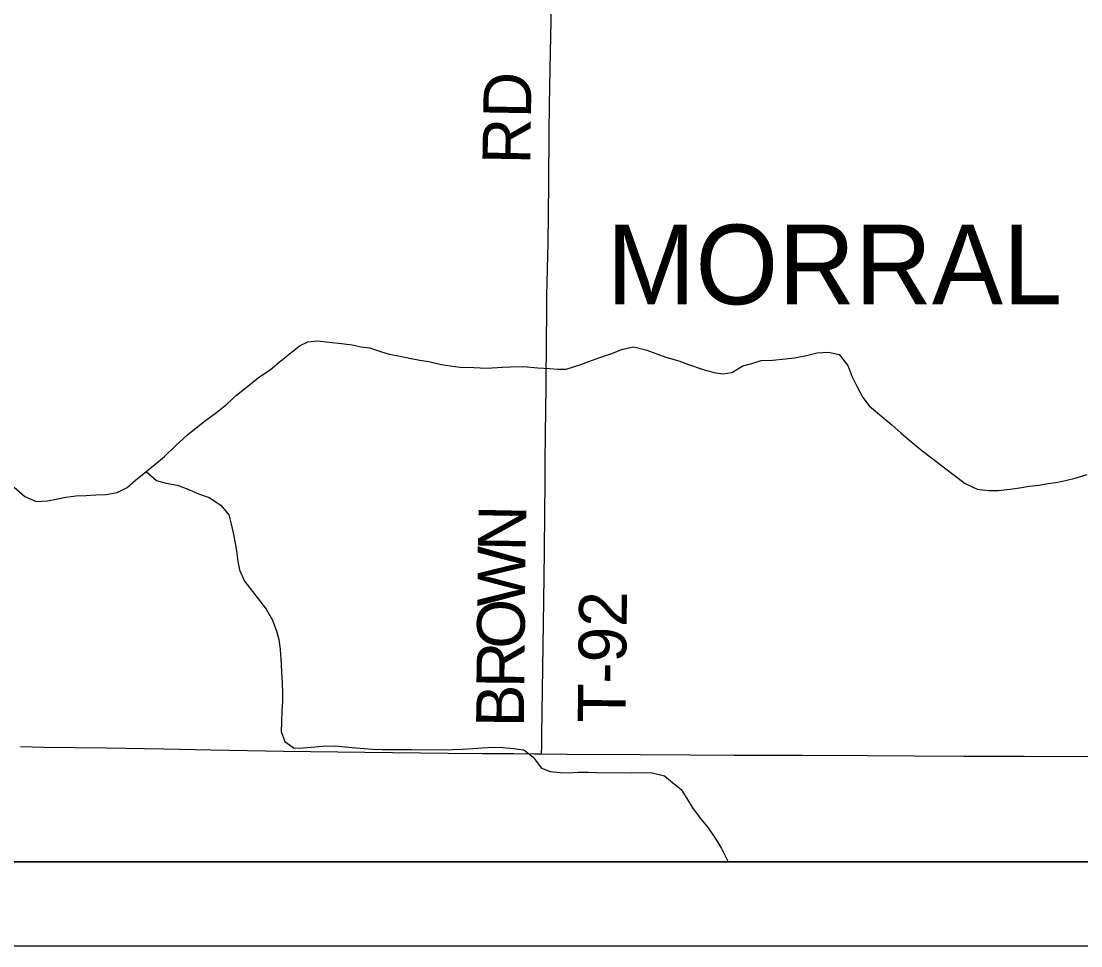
# Model space of a CAD drawing. Extents: x -17 to 88, y -5 to 22.
# Drawn here: x -14.14 to -12.88, y 14 to 15.1 of the extents above; entities that cross this region are included whole.
import ezdxf

# ---------------------------------------------------------------- set-up
doc = ezdxf.new("R2010")
doc.units = 0
for name, color, linetype in [('Default', 7, 'Continuous'), ('GM_X_Corporation_Text', 7, 'Continuous'), ('GM_X_Minor_River', 7, 'Continuous'), ('GM_X_State_Route', 7, 'Continuous'), ('GM_X_Township_Road', 7, 'Continuous'), ('GM_X_Township_Road_Text', 7, 'Continuous'), ('SH_Data', 7, 'Continuous')]:
    doc.layers.add(name, color=color, linetype=linetype)

msp = doc.modelspace()

# ---------------------------------------------------------------- linework, layer by layer
at = {"layer": 'Default'}
msp.add_lwpolyline([(-17.1602, 20.9), (-10.3602, 20.9), (-10.3602, 14.1), (-17.1602, 14.1)], close=True, dxfattribs=at)
at = {"layer": 'GM_X_Minor_River'}
for points in [[(-14.1487, 14.5458), (-14.1359, 14.5347), (-14.1227, 14.5288), (-14.109, 14.5294), (-14.0969, 14.5316), (-14.0874, 14.5338), (-14.0752, 14.5352), (-14.0631, 14.5358), (-14.0517, 14.5365), (-14.0392, 14.5371), (-14.0263, 14.5392), (-14.0144, 14.5452), (-14.0045, 14.5542), (-13.9922, 14.5639), (-13.9812, 14.5726), (-13.9697, 14.5823), (-13.9567, 14.5947), (-13.9425, 14.6079), (-13.9322, 14.6161), (-13.9211, 14.6251), (-13.9096, 14.6333), (-13.8959, 14.6446), (-13.8844, 14.6551), (-13.8568, 14.6769), (-13.8442, 14.6851), (-13.8335, 14.6945), (-13.8217, 14.7038), (-13.8091, 14.714), (-13.7995, 14.7184), (-13.7878, 14.7198), (-13.7738, 14.7181), (-13.7594, 14.7165), (-13.7465, 14.7152), (-13.7359, 14.7128), (-13.726, 14.7116), (-13.7128, 14.7069), (-13.7026, 14.7038), (-13.6894, 14.7017), (-13.6765, 14.6989), (-13.6659, 14.6969), (-13.6553, 14.6953), (-13.6409, 14.6917), (-13.6299, 14.6901), (-13.6182, 14.6885), (-13.6019, 14.6879), (-13.5867, 14.6874), (-13.5678, 14.6883), (-13.5583, 14.689), (-13.5427, 14.6892), (-13.5257, 14.6875), (-13.5117, 14.687), (-13.5018, 14.6861), (-13.492, 14.686), (-13.4745, 14.6916), (-13.4649, 14.6953), (-13.452, 14.7001), (-13.4375, 14.7049), (-13.425, 14.71), (-13.4113, 14.7126), (-13.3962, 14.7086), (-13.3852, 14.7047), (-13.3735, 14.7004)], [(-13.3735, 14.7004), (-13.358, 14.6961), (-13.3463, 14.6918), (-13.33, 14.6859), (-13.3164, 14.682), (-13.3054, 14.6807), (-13.2948, 14.6821), (-13.2818, 14.69), (-13.2712, 14.6929), (-13.2598, 14.6962), (-13.2465, 14.6968), (-13.2309, 14.6982), (-13.2203, 14.6996), (-13.2059, 14.7025), (-13.1933, 14.7054), (-13.18, 14.7064), (-13.1672, 14.7036), (-13.1567, 14.6906), (-13.1523, 14.6777), (-13.1463, 14.6658), (-13.1389, 14.6525), (-13.1314, 14.6425), (-13.119, 14.6318), (-13.1047, 14.6198), (-13.0934, 14.6099), (-13.0829, 14.601), (-13.069, 14.5895), (-13.0558, 14.5795), (-13.0419, 14.5687), (-13.0303, 14.5599), (-13.0171, 14.5502), (-13.0031, 14.5433), (-12.9895, 14.5416), (-12.9781, 14.5419), (-12.9637, 14.5432), (-12.9527, 14.545), (-12.9413, 14.5468), (-12.9295, 14.5482), (-12.9185, 14.55), (-12.9071, 14.5518), (-12.8965, 14.5539), (-12.8866, 14.5565), (-12.8721, 14.5609)], [(-13.9917, 14.5644), (-13.9795, 14.5536), (-13.9677, 14.5504), (-13.9545, 14.548), (-13.9401, 14.5425), (-13.9296, 14.5379), (-13.9167, 14.5332), (-13.9028, 14.5243), (-13.8934, 14.5128), (-13.8905, 14.5018), (-13.888, 14.4915), (-13.8855, 14.4771), (-13.884, 14.4668), (-13.8826, 14.4573), (-13.8805, 14.4474), (-13.8745, 14.434), (-13.8652, 14.4214), (-13.8569, 14.4107), (-13.8491, 14.4007), (-13.8413, 14.3874), (-13.8365, 14.3744), (-13.8339, 14.3645), (-13.8321, 14.3524), (-13.8312, 14.3349), (-13.8305, 14.325), (-13.8299, 14.3128), (-13.8293, 14.3011), (-13.8294, 14.2901), (-13.8302, 14.2798), (-13.8308, 14.2658), (-13.8309, 14.2551), (-13.8268, 14.243), (-13.8155, 14.2352), (-13.8049, 14.2355), (-13.7954, 14.2362), (-13.7814, 14.2376), (-13.7666, 14.2378), (-13.7548, 14.2369), (-13.7423, 14.2356), (-13.7226, 14.2339), (-13.7109, 14.2334), (-13.6991, 14.2337), (-13.6752, 14.2334), (-13.6407, 14.2331), (-13.6271, 14.2337), (-13.6153, 14.234), (-13.6032, 14.2346), (-13.5918, 14.2356), (-13.5789, 14.2363), (-13.5671, 14.2358), (-13.5546, 14.2349), (-13.5425, 14.2332), (-13.5312, 14.2244), (-13.5215, 14.2114), (-13.5109, 14.2075), (-13.4992, 14.2062), (-13.4886, 14.2057), (-13.4776, 14.2064), (-13.4654, 14.2066), (-13.456, 14.2061), (-13.4146, 14.2057), (-13.4025, 14.206), (-13.3896, 14.2059), (-13.3752, 14.2023), (-13.3655, 14.1942), (-13.3553, 14.1858), (-13.3486, 14.1751), (-13.3415, 14.164), (-13.3325, 14.1517), (-13.3232, 14.1403), (-13.3146, 14.128), (-13.3071, 14.1158), (-13.3004, 14.1024), (-13.2991, 14.1)]]:
    msp.add_lwpolyline(points, dxfattribs=at)
at = {"layer": 'GM_X_State_Route'}
for points in [[(-14.1413, 14.237), (-14.1134, 14.2365), (-14.0762, 14.236), (-14.0389, 14.2355), (-13.9706, 14.2344), (-13.9148, 14.2331), (-13.8279, 14.2316), (-13.7317, 14.2304), (-13.6323, 14.2291), (-13.592, 14.2288), (-13.5547, 14.2287), (-13.5299, 14.2284), (-13.5212, 14.2284)], [(-13.5212, 14.2284), (-13.4908, 14.228), (-13.4038, 14.2278), (-13.3448, 14.2274), (-13.292, 14.227), (-13.2675, 14.227), (-13.2516, 14.227), (-13.2112, 14.2269), (-13.1336, 14.2263), (-13.0777, 14.2262), (-13.0187, 14.2257), (-12.9472, 14.2256), (-12.8292, 14.2254)]]:
    msp.add_lwpolyline(points, dxfattribs=at)
at = {"layer": 'GM_X_Township_Road'}
msp.add_lwpolyline([(-13.5212, 14.2284), (-13.5211, 14.2381), (-13.521, 14.2514), (-13.5202, 14.3043), (-13.5194, 14.3572), (-13.5185, 14.4101), (-13.5179, 14.4692), (-13.5172, 14.5158), (-13.517, 14.55), (-13.5169, 14.5749), (-13.5165, 14.6091), (-13.5159, 14.6651), (-13.5153, 14.7242), (-13.5151, 14.7491), (-13.5149, 14.7739), (-13.5147, 14.7895), (-13.5136, 14.8361), (-13.5131, 14.8703), (-13.5128, 14.9077), (-13.5123, 14.9668), (-13.5118, 15.001), (-13.5105, 15.0632), (-13.5095, 15.1192)], dxfattribs=at)
at = {"layer": 'SH_Data'}
for p, q in [((-17.1602, 14.1), (-10.3602, 14.1)), ((-17.2602, 14), (-10.2602, 14))]:
    msp.add_line(p, q, dxfattribs=at)

# ---------------------------------------------------------------- texts
at = {"layer": 'GM_X_Corporation_Text'}
msp.add_text('MORRAL', height=0.0947, rotation=0, dxfattribs=at).set_placement((-13.4437, 14.7633))
at = {"layer": 'GM_X_Township_Road_Text'}
for s, height, rotation, p in [('RD', 0.05682, 89.014, (-13.5349, 14.9295)), ('N', 0.0568, 88.816, (-13.5404, 14.4689)), ('W', 0.0568, 89.4383, (-13.541, 14.4033)), ('T-92', 0.05682, 89.2931, (-13.4215, 14.2652)), ('O', 0.0568, 89.439, (-13.5415, 14.3533)), ('R', 0.0568, 89.4412, (-13.542, 14.3066)), ('B', 0.0568, 89.4379, (-13.5424, 14.2599))]:
    msp.add_text(s, height=height, rotation=rotation, dxfattribs=at).set_placement(p)

doc.saveas('drawing.dxf')
